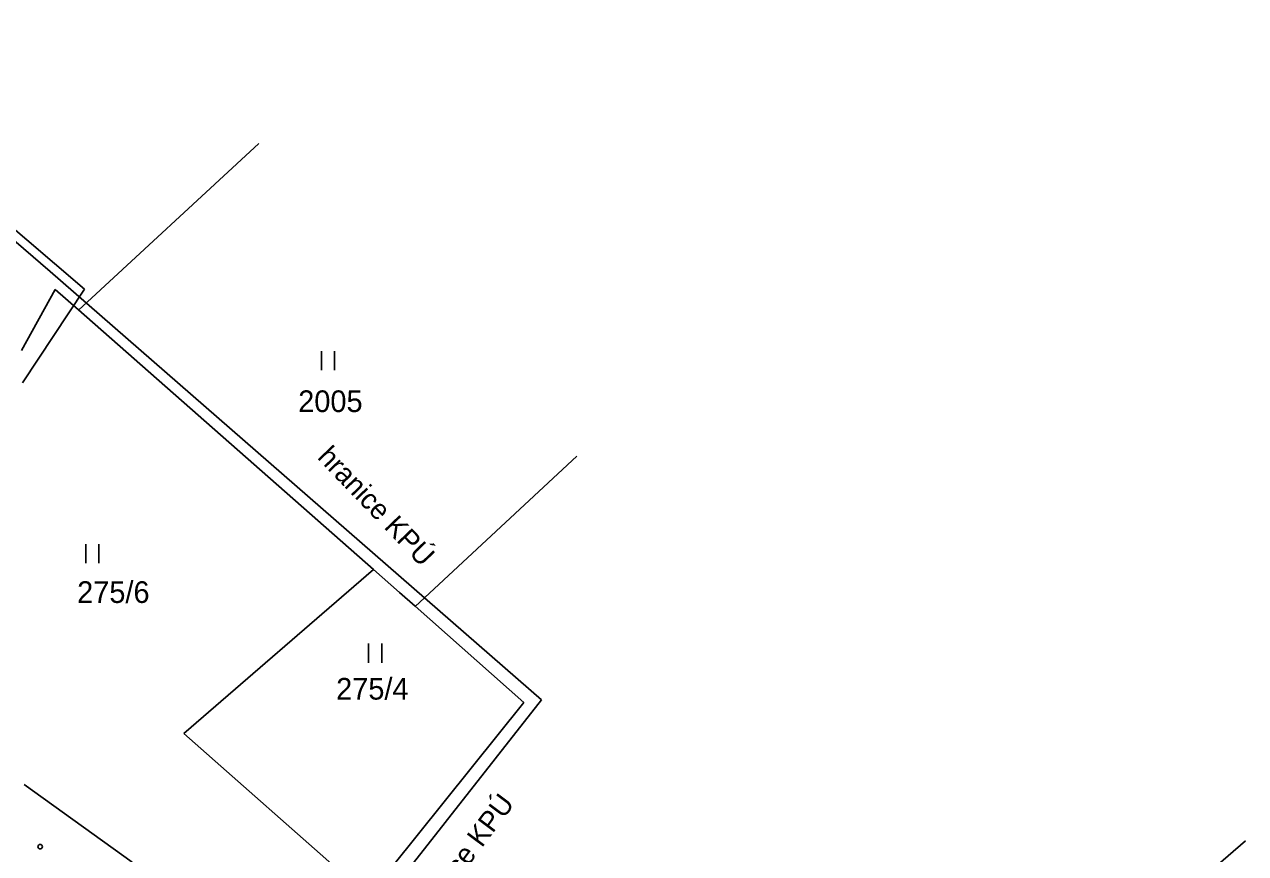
# Model space of a CAD drawing. Extents: x -815878 to -812162, y -1076286 to -1072327.
# Drawn here: x -813682.6 to -813586.7, y -1073995.6 to -1073930.5 of the extents above; entities that cross this region are included whole.
import ezdxf

# ---------------------------------------------------------------- set-up
doc = ezdxf.new("R2010")
doc.units = 0
for name, color, linetype in [('Vrstva 1', 7, 'Continuous'), ('Vrstva 18', 7, 'Continuous'), ('Vrstva 25', 7, 'Continuous'), ('Vrstva 56', 7, 'Continuous'), ('Vrstva 62', 7, 'Continuous')]:
    doc.layers.add(name, color=color, linetype=linetype)

msp = doc.modelspace()

# ---------------------------------------------------------------- linework, layer by layer
at = {"layer": 'Vrstva 1'}
for p, q in [((-813677.88, -1073951.31), (-813702.34, -1073930.53)), ((-813678.351, -1073952.971), (-813664.21, -1073939.88)), ((-813682.85, -1073956.13), (-813680.2, -1073951.34)), ((-813682.76, -1073958.67), (-813677.88, -1073951.31)), ((-813680.2, -1073951.34), (-813678.37, -1073952.95)), ((-813678.37, -1073952.95), (-813655.2, -1073973.33)), ((-813639.24, -1073964.44), (-813651.914, -1073976.227)), ((-813670.1, -1073986.21), (-813655.2, -1073973.33)), ((-813655.2, -1073973.33), (-813653.15, -1073975.13)), ((-813653.15, -1073975.13), (-813651.92, -1073976.22)), ((-813651.92, -1073976.22), (-813643.39, -1073983.78)), ((-813643.39, -1073983.78), (-813653.79, -1073996.73)), ((-813655.46, -1073999.12), (-813670.1, -1073986.21)), ((-813674.14, -1073996.32), (-813682.64, -1073990.22)), ((-813586.711, -1073994.639), (-813595.69, -1074002.35))]:
    msp.add_line(p, q, dxfattribs=at)
at = {"layer": 'Vrstva 25'}
for p, q in [((-813659.29, -1073956.185), (-813659.29, -1073957.685)), ((-813658.268, -1073957.685), (-813658.268, -1073956.185)), ((-813677.79, -1073971.345), (-813677.79, -1073972.845)), ((-813676.768, -1073972.845), (-813676.768, -1073971.345)), ((-813655.577, -1073979.155), (-813655.577, -1073980.655)), ((-813654.555, -1073980.655), (-813654.555, -1073979.155))]:
    msp.add_line(p, q, dxfattribs=at)
msp.add_circle((-813681.37, -1073995.1), 0.175, dxfattribs=at)
at = {"layer": 'Vrstva 62'}
for p, q in [((-813680.58, -1073949.92), (-813703.1, -1073930.67)), ((-813642, -1073983.57), (-813680.58, -1073949.92)), ((-813659.82, -1074006.25), (-813642, -1073983.57))]:
    msp.add_line(p, q, dxfattribs=at)

# ---------------------------------------------------------------- texts
at = {"layer": 'Vrstva 18'}
for s, p in [('2005', (-813661.11, -1073960.97)), ('275/6', (-813678.471, -1073975.96)), ('275/4', (-813658.131, -1073983.55))]:
    msp.add_text(s, height=1.7, dxfattribs=at).set_placement(p)
at = {"layer": 'Vrstva 56'}
for rotation, p in [(313.79311, (-813659.678, -1073964.575)), (53.18353, (-813651.23, -1074001.3))]:
    msp.add_text('hranice KPÚ', height=1.59202, rotation=rotation, dxfattribs=at).set_placement(p)

doc.saveas('drawing.dxf')
